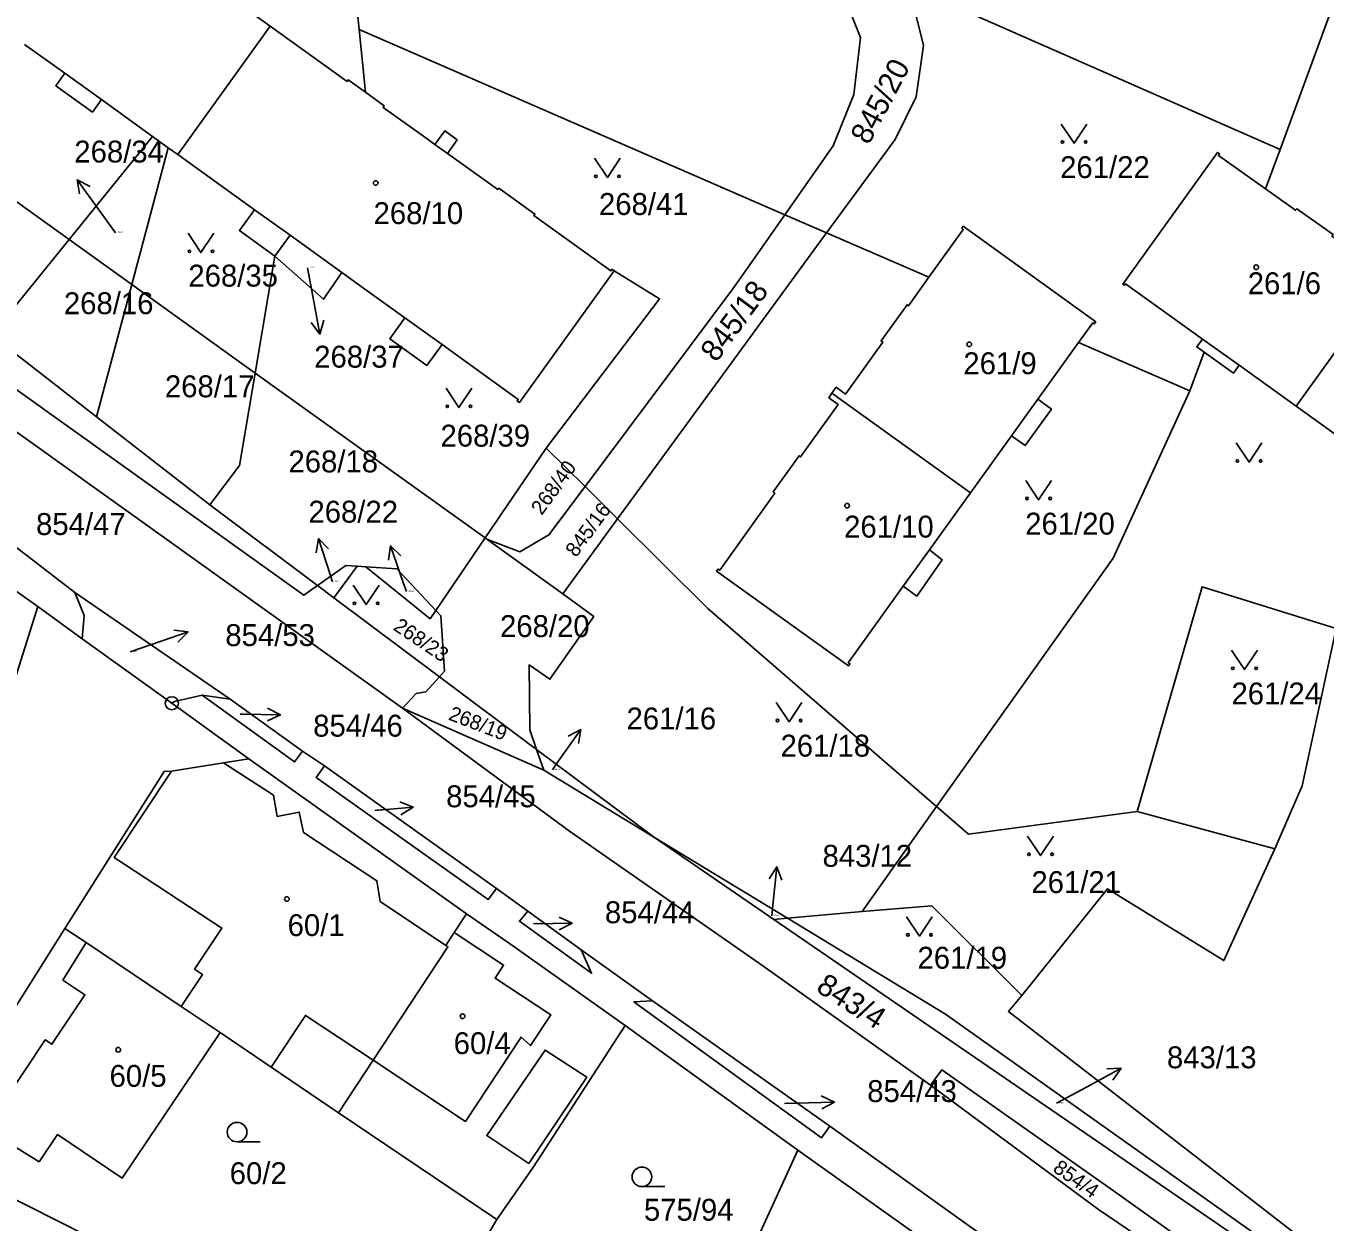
# Model space of a CAD drawing. Extents: x -737240 to -735272, y -1119606 to -1117878.
# Drawn here: x -737021.1 to -736920.3, y -1118809.6 to -1118716.8 of the extents above; entities that cross this region are included whole.
import ezdxf

# ---------------------------------------------------------------- set-up
doc = ezdxf.new("R2010")
doc.units = 0
for name, color, linetype in [('Level 1', 7, 'Continuous'), ('Level 16', 7, 'Continuous'), ('Level 18', 7, 'Continuous'), ('Level 19', 7, 'Continuous'), ('Level 25', 7, 'Continuous'), ('Level 4', 7, 'Continuous')]:
    doc.layers.add(name, color=color, linetype=linetype)

msp = doc.modelspace()

# ---------------------------------------------------------------- linework, layer by layer
at = {"layer": 'Level 1'}
for p, q in [((-736997.6, -1118693.96), (-736995.28, -1118717.04)), ((-736916.97, -1118707.69), (-736923.8, -1118726.36)), ((-736991.9, -1118769.72), (-737075.7, -1118709.74)), ((-736952.61, -1118713.67), (-736923.8, -1118726.36)), ((-737044, -1118714.5), (-737017.78, -1118733.33)), ((-737002.19, -1118716.77), (-737009.35, -1118726.75)), ((-736995.28, -1118717.04), (-736994.79, -1118721.9)), ((-736995.28, -1118717.04), (-736962.24, -1118731.41)), ((-737018.12, -1118720.43), (-737021.24, -1118718.2)), ((-737011.3, -1118725.34), (-737015.28, -1118722.47)), ((-737011.3, -1118725.34), (-737017.78, -1118733.33)), ((-737010.1, -1118726.21), (-737012.92, -1118736.82)), ((-737010.1, -1118726.21), (-737011.3, -1118725.34)), ((-737009.35, -1118726.75), (-737010.1, -1118726.21)), ((-737003.4, -1118731.02), (-737009.35, -1118726.75)), ((-736923.8, -1118726.36), (-736924.94, -1118729.4)), ((-736962.24, -1118731.41), (-736958.99, -1118732.82)), ((-737017.78, -1118733.33), (-737023.81, -1118740.76)), ((-737017.78, -1118733.33), (-737012.92, -1118736.82)), ((-737000.64, -1118733), (-737001.81, -1118734.62)), ((-736996.61, -1118735.9), (-737000.64, -1118733)), ((-736975.22, -1118755.02), (-736958.99, -1118732.82)), ((-736958.99, -1118732.82), (-736951.05, -1118736.27)), ((-737001.81, -1118734.62), (-737003.34, -1118743.7)), ((-736914.99, -1118735.74), (-736922.55, -1118746.28)), ((-737012.92, -1118736.82), (-737015.66, -1118747.1)), ((-737012.92, -1118736.82), (-737003.34, -1118743.7)), ((-737023.81, -1118740.76), (-737015.66, -1118747.1)), ((-736939.44, -1118741.33), (-736942.6, -1118745.73)), ((-736939.44, -1118741.33), (-736930.81, -1118745.08)), ((-736929.69, -1118742.08), (-736930.81, -1118745.08)), ((-736922.55, -1118746.28), (-736926.98, -1118743.1)), ((-737003.34, -1118743.7), (-736985.5, -1118756.5)), ((-736947.82, -1118752.99), (-736958.58, -1118745.26)), ((-736918.13, -1118749.46), (-736922.55, -1118746.28)), ((-737015.66, -1118747.1), (-737006.87, -1118753.94)), ((-736944.64, -1118748.57), (-736947.82, -1118752.99)), ((-736980.75, -1118749.52), (-736985.5, -1118756.5)), ((-736980.75, -1118749.52), (-736977.74, -1118752.51)), ((-736977.74, -1118752.51), (-736975.22, -1118755.02)), ((-736947.82, -1118752.99), (-736951, -1118757.41)), ((-737006.87, -1118753.94), (-736998.51, -1118760.19)), ((-736979.47, -1118760.83), (-736975.22, -1118755.02)), ((-736985.5, -1118756.5), (-736989.33, -1118762.12)), ((-736985.5, -1118756.5), (-736985.36, -1118756.6)), ((-737026.38, -1118757.49), (-737020.22, -1118761.82)), ((-736985.36, -1118756.6), (-736979.47, -1118760.83)), ((-736995.42, -1118758.69), (-736997.24, -1118761.14)), ((-736994.76, -1118758.74), (-736995.42, -1118758.69)), ((-736998.51, -1118760.19), (-736997.24, -1118761.14)), ((-737005.29, -1118769.01), (-737017.33, -1118760.72)), ((-736997.24, -1118761.14), (-736989.05, -1118767.27)), ((-737020.22, -1118761.82), (-737026.07, -1118780.39)), ((-737020.22, -1118761.82), (-737016.76, -1118764.32)), ((-736989.05, -1118767.27), (-736981.5, -1118772.91)), ((-737009.81, -1118769.33), (-737003.83, -1118773.64)), ((-737007.45, -1118768.71), (-737005.29, -1118769.01)), ((-736999.67, -1118773.05), (-737005.29, -1118769.01)), ((-736991.9, -1118769.72), (-736980.95, -1118774.53)), ((-737005.8, -1118773.96), (-737003.83, -1118773.64)), ((-737003.83, -1118773.64), (-736986.94, -1118785.68)), ((-736997.97, -1118774.19), (-736999.67, -1118773.05)), ((-736980.95, -1118774.53), (-736981.5, -1118772.91)), ((-736981.5, -1118772.91), (-736972.36, -1118779.75)), ((-737009.84, -1118774.61), (-737005.8, -1118773.96)), ((-736984.62, -1118783.7), (-736997.97, -1118774.19)), ((-736980.95, -1118774.53), (-736972.36, -1118779.75)), ((-736950.46, -1118777.35), (-736956.24, -1118785.48)), ((-736934.9, -1118777.74), (-736924.21, -1118780.64)), ((-736962.04, -1118786.01), (-736972.36, -1118779.75)), ((-736972.36, -1118779.75), (-736963.09, -1118786.11)), ((-736982.18, -1118785.47), (-736984.62, -1118783.7)), ((-736986.94, -1118785.68), (-736987.89, -1118787.13)), ((-736978.05, -1118788.47), (-736982.18, -1118785.47)), ((-736956.24, -1118785.48), (-736962.04, -1118786.01)), ((-736962.04, -1118786.01), (-736963.09, -1118786.11)), ((-737016.47, -1118787.91), (-737018.11, -1118786.8)), ((-736987.89, -1118787.13), (-736988.54, -1118788.12)), ((-737009.1, -1118792.87), (-737016.47, -1118787.91)), ((-736972.51, -1118792.43), (-736978.05, -1118788.47)), ((-736958.73, -1118802.15), (-736972.51, -1118792.43)), ((-737006.06, -1118794.88), (-737009.1, -1118792.87)), ((-736974.63, -1118794.33), (-736961.22, -1118804.01)), ((-737002.11, -1118797.58), (-737006.06, -1118794.88)), ((-736996.87, -1118801.11), (-737002.11, -1118797.58)), ((-736994.19, -1118797.04), (-736996.87, -1118801.11)), ((-736996.87, -1118801.11), (-736984.58, -1118809.4)), ((-737011.78, -1118812.97), (-737029.98, -1118803.82)), ((-736967.81, -1118818.35), (-736961.22, -1118804.01)), ((-736961.22, -1118804.01), (-736941.01, -1118818.38)), ((-736984.58, -1118809.4), (-736990.53, -1118819.26))]:
    msp.add_line(p, q, dxfattribs=at)
for points in [[(-736961.29, -1118709.88), (-736957.89, -1118713.79), (-736956.36, -1118717.65), (-736956.88, -1118722.08), (-736958.49, -1118726.07), (-736962.24, -1118731.41)], [(-737009.24, -1118711.52), (-737008.1, -1118712.34), (-737008.19, -1118712.46), (-737002.19, -1118716.77)], [(-737061.64, -1118712.26), (-737062.56, -1118715.89), (-736999.57, -1118760.94), (-736998.51, -1118760.19)], [(-736958.99, -1118732.82), (-736953.68, -1118725.56), (-736952.03, -1118722.26), (-736951.48, -1118718.28), (-736952.61, -1118713.67)], [(-737002.19, -1118716.77), (-736996.21, -1118721.06), (-736996.12, -1118720.94), (-736994.79, -1118721.9)], [(-737015.28, -1118722.47), (-737015.98, -1118723.45), (-737018.82, -1118721.4), (-737018.12, -1118720.43)], [(-736994.79, -1118721.9), (-736993.32, -1118722.96), (-736993.41, -1118723.08), (-736990.29, -1118725.32), (-736989.39, -1118725.96)], [(-736989.39, -1118725.96), (-736988.63, -1118724.91), (-736987.66, -1118725.61), (-736988.41, -1118726.66)], [(-736988.41, -1118726.66), (-736984.52, -1118729.46), (-736984.43, -1118729.34), (-736981.63, -1118731.36), (-736981.71, -1118731.48), (-736975.74, -1118735.77), (-736975.66, -1118735.64), (-736975.49, -1118735.76)], [(-736929.82, -1118741.06), (-736935.79, -1118736.77), (-736935.88, -1118736.89), (-736936, -1118736.81), (-736928.65, -1118726.58), (-736928.49, -1118726.69), (-736928.58, -1118726.81), (-736924.94, -1118729.4)], [(-736924.94, -1118729.4), (-736922.59, -1118731.07), (-736922.5, -1118730.95), (-736919.69, -1118732.95), (-736919.78, -1118733.07), (-736915.71, -1118735.97), (-736915.36, -1118735.48), (-736914.99, -1118735.74)], [(-737001.81, -1118734.62), (-737004.57, -1118732.64), (-737003.4, -1118731.02)], [(-736962.24, -1118731.41), (-736965.22, -1118735.65), (-736966.28, -1118737.17), (-736977.74, -1118752.51)], [(-736951.05, -1118736.27), (-736948.39, -1118732.55), (-736948.51, -1118732.46), (-736948.39, -1118732.3), (-736938.1, -1118739.73), (-736938.22, -1118739.89), (-736938.34, -1118739.8), (-736939.44, -1118741.33)], [(-736996.61, -1118735.9), (-736998.03, -1118737.97), (-737001.81, -1118734.62)], [(-736991.72, -1118739.42), (-736994.65, -1118737.32), (-736996.61, -1118735.9)], [(-736975.49, -1118735.76), (-736982.84, -1118745.99), (-736983.01, -1118745.87), (-736982.92, -1118745.75), (-736988.84, -1118741.49)], [(-736975.49, -1118735.76), (-736971.96, -1118737.93), (-736980.75, -1118749.52)], [(-736958.58, -1118745.26), (-736958.25, -1118744.8), (-736957.52, -1118745.33), (-736954.64, -1118741.3), (-736954.76, -1118741.21), (-736952.75, -1118738.4), (-736952.63, -1118738.49), (-736951.05, -1118736.27)], [(-736988.84, -1118741.49), (-736990.01, -1118743.11), (-736992.89, -1118741.04), (-736991.72, -1118739.42)], [(-736929.69, -1118742.08), (-736930.26, -1118741.67), (-736929.82, -1118741.06)], [(-736926.98, -1118743.1), (-736927.42, -1118743.71), (-736929.69, -1118742.08)], [(-737017.33, -1118760.72), (-737025.5, -1118754.48), (-737034.32, -1118748.14), (-737043.29, -1118744.21), (-737045.38, -1118744)], [(-737003.34, -1118743.7), (-737004.55, -1118750.87), (-737006.87, -1118753.94)], [(-736953.05, -1118760.25), (-736957.31, -1118766.18), (-736957.19, -1118766.26), (-736957.3, -1118766.43), (-736967.53, -1118759.07), (-736967.41, -1118758.91), (-736967.29, -1118759), (-736963.02, -1118753.02), (-736963.14, -1118752.93), (-736961.13, -1118750.12), (-736961.01, -1118750.21), (-736958.1, -1118746.14), (-736958.83, -1118745.62), (-736958.58, -1118745.26)], [(-736930.81, -1118745.08), (-736936.74, -1118758.06), (-736950.46, -1118777.35)], [(-736942.6, -1118745.73), (-736941.54, -1118746.49), (-736943.59, -1118749.33), (-736944.64, -1118748.57)], [(-736977.74, -1118752.51), (-736980.55, -1118756.26), (-736982.79, -1118757.57), (-736985.36, -1118756.6)], [(-736975.22, -1118755.02), (-736968.22, -1118761.97), (-736950.46, -1118777.35)], [(-736951, -1118757.41), (-736950.02, -1118758.19), (-736951.99, -1118761.01), (-736953.05, -1118760.25)], [(-736995.42, -1118758.69), (-736996.3, -1118758.63), (-736998.51, -1118760.19)], [(-736989.33, -1118762.12), (-736992.34, -1118758.9), (-736994.76, -1118758.74)], [(-736994.76, -1118758.74), (-736989.77, -1118762.77), (-736989.33, -1118762.12)], [(-736934.9, -1118777.74), (-736929.85, -1118760.29), (-736919.44, -1118763.52)], [(-737017.33, -1118760.72), (-737016.61, -1118762.51), (-737016.76, -1118764.32)], [(-736981.5, -1118772.91), (-736982.02, -1118771.4), (-736982.08, -1118766.35), (-736980.47, -1118767.46), (-736977.06, -1118762.6), (-736979.47, -1118760.83)], [(-736989.05, -1118767.27), (-736988.66, -1118766.84), (-736988.94, -1118762.54), (-736989.33, -1118762.12)], [(-736919.44, -1118763.52), (-736922.09, -1118775.73), (-736924.21, -1118780.64)], [(-737016.76, -1118764.32), (-737013.2, -1118766.88), (-737009.81, -1118769.33)], [(-736989.05, -1118767.27), (-736990.1, -1118768.43), (-736990.84, -1118768.56), (-736991.9, -1118769.72)], [(-737009.81, -1118769.33), (-737009.61, -1118769.18), (-737007.45, -1118768.71)], [(-736999.67, -1118773.05), (-737000.28, -1118773.88), (-737007.45, -1118768.71)], [(-736950.93, -1118798.96), (-736963.95, -1118789.71), (-736978.95, -1118779.26), (-736991.9, -1118769.72)], [(-737018.11, -1118786.8), (-737010.41, -1118774.62), (-737009.84, -1118774.61)], [(-736984.62, -1118783.7), (-736985.26, -1118784.55), (-736998.6, -1118775.08), (-736997.97, -1118774.19)], [(-736950.46, -1118777.35), (-736947.99, -1118779.49), (-736934.9, -1118777.74)], [(-736924.21, -1118780.64), (-736928.17, -1118789.3), (-736937.18, -1118783.72), (-736943.85, -1118792.01)], [(-736986.94, -1118785.68), (-736983.54, -1118788.02), (-736974.63, -1118794.33)], [(-736978.05, -1118788.47), (-736977.24, -1118790.29), (-736982.83, -1118786.25), (-736982.18, -1118785.47)], [(-736956.24, -1118785.48), (-736950.82, -1118785.04), (-736943.85, -1118792.01)], [(-736963.09, -1118786.11), (-736916.05, -1118818.37), (-736911.54, -1118820.16)], [(-736919.53, -1118814.93), (-736949.76, -1118793.47), (-736962.04, -1118786.01)], [(-737029.98, -1118803.82), (-737026.81, -1118800.48), (-737023.61, -1118795.5), (-737018.11, -1118786.8)], [(-737016.47, -1118787.91), (-737018.27, -1118790.81), (-737016.56, -1118791.95), (-737019.12, -1118795.79), (-737019.64, -1118795.45), (-737024.26, -1118802.36), (-737020.11, -1118804.92), (-737018.69, -1118802.81), (-737013.66, -1118806.18), (-737006.06, -1118794.88)], [(-736988.54, -1118788.12), (-736988.38, -1118788.23), (-736994.19, -1118797.04)], [(-736958.73, -1118802.15), (-736959.38, -1118803.05), (-736973.95, -1118792.49), (-736972.51, -1118792.43)], [(-736943.85, -1118792.01), (-736944.88, -1118793.25), (-736918.69, -1118813.53)], [(-736974.63, -1118794.33), (-736981.73, -1118805.31), (-736984.58, -1118809.4)], [(-736921.26, -1118819.89), (-736920.76, -1118818.53), (-736936.91, -1118807.04), (-736950.05, -1118797.77), (-736950.93, -1118798.96)], [(-736921.26, -1118819.89), (-736937.9, -1118808.61), (-736950.93, -1118798.96)], [(-736920.41, -1118829.43), (-736925.17, -1118826.03), (-736939.16, -1118816.18), (-736958.73, -1118802.15)]]:
    msp.add_lwpolyline(points, dxfattribs=at)
at = {"layer": 'Level 16'}
for p, q in [((-736994.06, -1118777.64), (-736991.07, -1118777.399)), ((-736981.75, -1118786.45), (-736978.75, -1118786.403))]:
    msp.add_line(p, q, dxfattribs=at)
for points in [[(-737016.975, -1118729.799), (-737017.153, -1118728.696), (-737016.163, -1118729.215)], [(-737014.19, -1118732.81), (-737015.4, -1118731.13), (-737017.153, -1118728.696)], [(-736999.28, -1118735.53), (-736998.87, -1118737.72), (-736998.319, -1118740.669)], [(-736998.011, -1118739.594), (-736998.319, -1118740.669), (-736998.994, -1118739.778)], [(-736998.604, -1118757.653), (-736998.438, -1118756.547), (-736997.653, -1118757.343)], [(-736997.35, -1118759.9), (-736997.51, -1118759.4), (-736998.438, -1118756.547)], [(-736992.993, -1118758.228), (-736992.852, -1118757.119), (-736992.049, -1118757.897)], [(-736991.61, -1118760.66), (-736991.86, -1118759.95), (-736992.852, -1118757.119)], [(-737013.04, -1118765.35), (-737011.39, -1118764.77), (-737008.555, -1118763.789)], [(-737009.664, -1118763.643), (-737008.555, -1118763.789), (-737009.336, -1118764.588)], [(-737004.51, -1118770.17), (-737004.39, -1118770.17), (-737001.39, -1118770.222)], [(-737002.382, -1118769.705), (-737001.39, -1118770.222), (-737002.399, -1118770.705)], [(-736980.28, -1118774.5), (-736979.8, -1118773.81), (-736978.073, -1118771.357)], [(-736979.058, -1118771.887), (-736978.073, -1118771.357), (-736978.24, -1118772.462)], [(-736992.107, -1118776.981), (-736991.07, -1118777.399), (-736992.026, -1118777.978)], [(-736963.464, -1118782.959), (-736962.865, -1118782.016), (-736962.469, -1118783.061)], [(-736963.25, -1118785.83), (-736963.17, -1118785), (-736962.865, -1118782.016)], [(-736979.758, -1118785.919), (-736978.75, -1118786.403), (-736979.742, -1118786.919)], [(-736941.15, -1118800.38), (-736938.77, -1118799.09), (-736936.132, -1118797.661)], [(-736937.25, -1118797.698), (-736936.132, -1118797.661), (-736936.773, -1118798.577)], [(-736959.406, -1118799.811), (-736958.391, -1118800.281), (-736959.376, -1118800.81)], [(-736962.27, -1118800.4), (-736961.39, -1118800.37), (-736958.391, -1118800.281)]]:
    msp.add_lwpolyline(points, dxfattribs=at)
at = {"layer": 'Level 25'}
for p, q in [((-737002.968, -1118803.37), (-737004.75, -1118803.37)), ((-736971.548, -1118806.84), (-736973.33, -1118806.84))]:
    msp.add_line(p, q, dxfattribs=at)
for points in [[(-736938.79, -1118724.37), (-736939.79, -1118725.87), (-736940.79, -1118724.37)], [(-736975.01, -1118727.03), (-736976.01, -1118728.53), (-736977.01, -1118727.03)], [(-737006.55, -1118732.85), (-737007.55, -1118734.35), (-737008.55, -1118732.85)], [(-736986.53, -1118744.88), (-736987.53, -1118746.38), (-736988.53, -1118744.88)], [(-736925.21, -1118749.12), (-736926.21, -1118750.62), (-736927.21, -1118749.12)], [(-736941.54, -1118752.04), (-736942.54, -1118753.54), (-736943.54, -1118752.04)], [(-736993.73, -1118760.17), (-736994.73, -1118761.67), (-736995.73, -1118760.17)], [(-736925.56, -1118765.22), (-736926.56, -1118766.72), (-736927.56, -1118765.22)], [(-736960.91, -1118769.27), (-736961.91, -1118770.77), (-736962.91, -1118769.27)], [(-736941.39, -1118779.65), (-736942.39, -1118781.15), (-736943.39, -1118779.65)], [(-736950.79, -1118785.9), (-736951.79, -1118787.4), (-736952.79, -1118785.9)]]:
    msp.add_lwpolyline(points, dxfattribs=at)
for centre in [(-736940.69, -1118725.77), (-736938.89, -1118725.77), (-736976.91, -1118728.43), (-736975.11, -1118728.43), (-737008.45, -1118734.25), (-737006.65, -1118734.25), (-736988.43, -1118746.28), (-736986.63, -1118746.28), (-736927.11, -1118750.52), (-736925.31, -1118750.52), (-736943.44, -1118753.44), (-736941.64, -1118753.44), (-736995.63, -1118761.57), (-736993.83, -1118761.57), (-736927.46, -1118766.62), (-736925.66, -1118766.62), (-736962.81, -1118770.67), (-736961.01, -1118770.67), (-736943.29, -1118781.05), (-736941.49, -1118781.05), (-736952.69, -1118787.3), (-736950.89, -1118787.3)]:
    msp.add_circle(centre, 0.1, dxfattribs=at)
for centre, major_axis, ratio in [((-736993.99, -1118728.95), (0.18, 0), 0.9848078), ((-736925.65, -1118735.49), (0.18, 0), 0.9848078), ((-736947.92, -1118741.47), (0.18, 0), 0.9848078), ((-736957.4, -1118753.99), (0.18, 0), 0.9848078), ((-737009.81, -1118769.33), (0.516, 0), 0.9848078), ((-737009.81, -1118769.33), (0.0375, 0), 0.9848078), ((-737000.88, -1118784.52), (0.18, 0), 0.9848078), ((-736987.25, -1118793.62), (0.18, 0), 0.9848078), ((-737013.97, -1118796.22), (0.18, 0), 0.9848078), ((-737004.75, -1118802.614), (0.764, 0), 0.9894236), ((-736973.33, -1118806.084), (0.764, 0), 0.9894236)]:
    msp.add_ellipse(centre, major_axis=major_axis, ratio=ratio, dxfattribs=at)
at = {"layer": 'Level 4'}
for p, q in [((-737018.12, -1118720.43), (-737015.28, -1118722.47)), ((-736989.39, -1118725.96), (-736988.41, -1118726.66)), ((-737000.64, -1118733), (-737003.4, -1118731.02)), ((-736991.72, -1118739.42), (-736988.84, -1118741.49)), ((-736929.82, -1118741.06), (-736926.98, -1118743.1)), ((-736942.6, -1118745.73), (-736944.64, -1118748.57)), ((-736951, -1118757.41), (-736953.05, -1118760.25))]:
    msp.add_line(p, q, dxfattribs=at)
for points in [[(-737009.1, -1118792.87), (-737007.44, -1118790.37), (-737008.05, -1118789.96), (-737005.93, -1118786.78), (-737014.28, -1118781.31), (-737009.84, -1118774.61)], [(-737005.8, -1118773.96), (-737001.93, -1118776.47), (-737001.63, -1118778.11), (-736999.92, -1118777.77), (-736999.59, -1118779.35), (-736993.9, -1118783.11), (-736993.64, -1118784.71), (-736988.54, -1118788.12)], [(-736987.89, -1118787.13), (-736984.07, -1118789.65), (-736984.72, -1118790.67), (-736980.4, -1118793.51), (-736981.97, -1118795.9), (-736982.7, -1118795.24), (-736987.03, -1118801.78), (-736994.19, -1118797.04)], [(-736994.19, -1118797.04), (-736999.44, -1118793.56), (-737002.11, -1118797.58)], [(-736982.1, -1118805.04), (-736977.61, -1118798.34), (-736980.84, -1118796.25), (-736985.37, -1118802.88), (-736982.1, -1118805.04)]]:
    msp.add_lwpolyline(points, dxfattribs=at)

# ---------------------------------------------------------------- texts
at = {"layer": 'Level 16'}
for s, p in [('268/34', (-737017.38, -1118727.36)), ('268/37', (-736998.76, -1118743.28)), ('854/47', (-737020.35, -1118756.27)), ('268/22', (-736999.21, -1118755.31)), ('854/53', (-737005.66, -1118764.89)), ('261/16', (-736974.52, -1118771.36)), ('854/46', (-736998.84, -1118771.92)), ('854/45', (-736988.52, -1118777.4)), ('843/12', (-736959.31, -1118782.02)), ('854/44', (-736976.2, -1118786.4)), ('843/13', (-736932.58, -1118797.66)), ('854/43', (-736955.84, -1118800.28))]:
    msp.add_text(s, height=1.7, dxfattribs=at).set_placement(p)
at = {"layer": 'Level 18'}
for s, height, rotation, p in [('845/20', 1.7, 62.05941, (-736955.725, -1118726.057)), ('845/18', 1.7, 53.66043, (-736967.549, -1118742.936)), ('268/40', 1.14, 53.93448, (-736981.103, -1118754.798)), ('845/16', 1.14, 53.66061, (-736978.437, -1118758.063)), ('268/23', 1.14, 325.99674, (-736992.702, -1118763.576)), ('268/19', 1.14, 339.01326, (-736988.413, -1118770.582)), ('843/4', 1.7, 327.20787, (-736959.904, -1118791.621)), ('854/4', 1.14, 324.8253, (-736941.505, -1118805.611))]:
    msp.add_text(s, height=height, rotation=rotation, dxfattribs=at).set_placement(p)
for s, height, p in [('261/22', 1.7, (-736940.87, -1118728.57)), ('268/41', 1.7, (-736976.66, -1118731.43)), ('268/34', 0.1, (-737014.04, -1118732.81)), ('268/35', 1.7, (-737008.53, -1118736.99)), ('268/37', 0.1, (-736999.13, -1118735.53)), ('268/16', 1.7, (-737018.19, -1118739.13)), ('268/17', 1.7, (-737010.35, -1118745.58)), ('268/39', 1.7, (-736988.96, -1118749.41)), ('268/18', 1.7, (-737000.76, -1118751.41)), ('261/20', 1.7, (-736943.58, -1118756.24)), ('268/22', 0.1, (-736997.2, -1118759.9)), ('268/24', 0.1, (-736991.46, -1118760.66)), ('268/20', 1.7, (-736984.34, -1118764.19)), ('854/53', 0.1, (-737012.89, -1118765.35)), ('261/24', 1.7, (-736927.57, -1118769.42)), ('854/46', 0.1, (-737004.36, -1118770.17)), ('261/18', 1.7, (-736962.57, -1118773.47)), ('261/16', 0.1, (-736980.13, -1118774.5)), ('854/45', 0.1, (-736993.91, -1118777.64)), ('261/21', 1.7, (-736943.1, -1118784.06)), ('843/12', 0.1, (-736963.1, -1118785.83)), ('854/44', 0.1, (-736981.6, -1118786.45)), ('261/19', 1.7, (-736951.94, -1118789.93)), ('854/43', 0.1, (-736962.12, -1118800.4)), ('843/13', 0.1, (-736941, -1118800.38)), ('60/2', 1.7, (-737005.32, -1118806.65)), ('575/94', 1.7, (-736973.17, -1118809.49))]:
    msp.add_text(s, height=height, dxfattribs=at).set_placement(p)
at = {"layer": 'Level 19'}
for s, p in [('268/10', (-736994.155, -1118732.14)), ('261/6', (-736926.31, -1118737.58)), ('261/9', (-736948.38, -1118743.79)), ('261/10', (-736957.635, -1118756.47)), ('60/1', (-737000.825, -1118787.4)), ('60/4', (-736987.935, -1118796.56)), ('60/5', (-737014.645, -1118799.1))]:
    msp.add_text(s, height=1.7, dxfattribs=at).set_placement(p)

doc.saveas('drawing.dxf')
